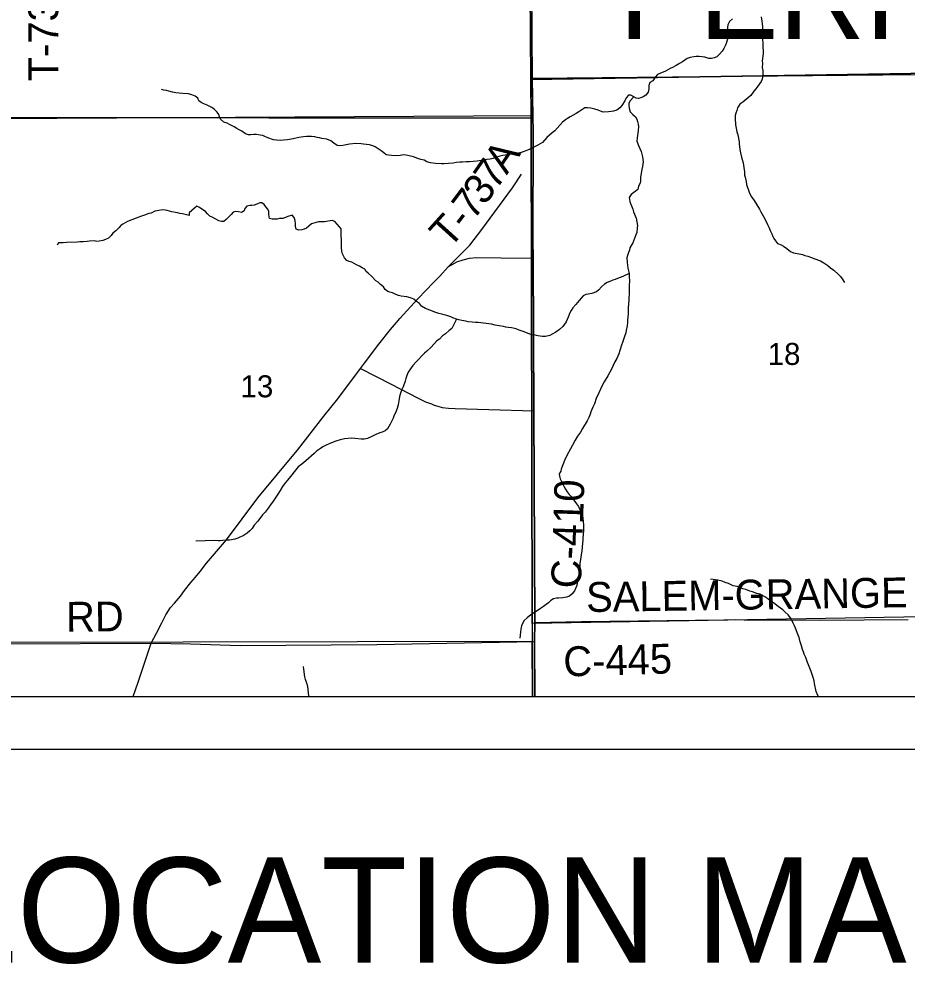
# Model space of a CAD drawing. Extents: x 0 to 34, y 0 to 22.
# Drawn here: x 4.579 to 6.27, y 13.591 to 15.389 of the extents above; entities that cross this region are included whole.
import ezdxf

# ---------------------------------------------------------------- set-up
doc = ezdxf.new("R2010")
doc.units = 0
for name, color, linetype in [('Default', 7, 'Continuous'), ('GM_X_County_Road', 7, 'Continuous'), ('GM_X_County_Road_Text', 7, 'Continuous'), ('GM_X_Minor_River', 7, 'Continuous'), ('GM_X_Rail_Line', 7, 'Continuous'), ('GM_X_Section', 7, 'Continuous'), ('GM_X_Section_Text', 7, 'Continuous'), ('GM_X_Township', 7, 'Continuous'), ('GM_X_Township_Road', 7, 'Continuous'), ('GM_X_Township_Road_Text', 7, 'Continuous'), ('GM_X_Township_Text', 7, 'Continuous'), ('SH_Cut_Line', 7, 'Continuous'), ('SH_Data', 7, 'Continuous'), ('SH_Text', 7, 'Continuous')]:
    doc.layers.add(name, color=color, linetype=linetype)

msp = doc.modelspace()

# ---------------------------------------------------------------- linework, layer by layer
at = {"layer": 'Default'}
for points in [[(5.5573, 14.1), (6.527, 14.1), (6.5252, 14.2552), (5.5565, 14.239), (5.5568, 14.2045)], [(4.5592, 14.1), (5.5573, 14.1), (5.5568, 14.2045), (4.5597, 14.2026)]]:
    msp.add_lwpolyline(points, close=True, dxfattribs=at)
at = {"layer": 'GM_X_County_Road'}
for points in [[(5.5581, 15.2023), (5.5581, 15.2044), (5.5571, 15.2755), (5.5558, 15.4469), (5.5556, 15.5593)], [(5.5617, 14.2409), (5.5597, 14.6434), (5.5585, 14.9341), (5.5583, 14.9671), (5.559, 15.1741), (5.5581, 15.2023)], [(5.5617, 14.2409), (5.6505, 14.2428), (5.9216, 14.2459), (5.9435, 14.2467), (5.9605, 14.2462), (6.1042, 14.2452), (6.2723, 14.2468)], [(5.5621, 14.1), (5.561, 14.2045), (5.5617, 14.2409)]]:
    msp.add_lwpolyline(points, dxfattribs=at)
at = {"layer": 'GM_X_Minor_River'}
for points in [[(5.9378, 15.3897), (5.9323, 15.3846), (5.929, 15.3781), (5.9287, 15.3735), (5.9288, 15.3682), (5.9293, 15.3636), (5.9294, 15.3587), (5.9291, 15.3534), (5.9266, 15.3446), (5.9245, 15.3392), (5.9212, 15.3327), (5.9183, 15.328), (5.9135, 15.3222), (5.9079, 15.3172), (5.9034, 15.3152), (5.8981, 15.3139), (5.8928, 15.3142), (5.8856, 15.3163), (5.8802, 15.3173), (5.8746, 15.318), (5.8689, 15.3178), (5.8647, 15.3174), (5.8576, 15.3157), (5.8519, 15.3137), (5.843, 15.3074), (5.8373, 15.3046), (5.8306, 15.3007), (5.8239, 15.2971), (5.8194, 15.2947), (5.8104, 15.2896), (5.7995, 15.2851), (5.795, 15.2835), (5.7905, 15.2785), (5.7861, 15.2715), (5.7809, 15.2684), (5.7787, 15.2623), (5.7789, 15.2562), (5.7775, 15.2497), (5.7731, 15.2439), (5.7682, 15.2407), (5.7633, 15.2391), (5.7592, 15.2379), (5.7546, 15.2382), (5.75, 15.2411), (5.7443, 15.2444), (5.7401, 15.2439), (5.7357, 15.2393), (5.7328, 15.2331), (5.7273, 15.2246), (5.7232, 15.22), (5.7176, 15.2153), (5.7112, 15.2136), (5.7071, 15.2128), (5.7021, 15.2123), (5.6915, 15.2121), (5.6866, 15.2135), (5.682, 15.2153), (5.6759, 15.2178), (5.6683, 15.2196), (5.6622, 15.2202), (5.6569, 15.2201), (5.6513, 15.2165), (5.6457, 15.2126), (5.6405, 15.2094), (5.6348, 15.2063), (5.6289, 15.2027), (5.624, 15.2), (5.6199, 15.1972), (5.6143, 15.1929), (5.6095, 15.1871), (5.5995, 15.1766), (5.5946, 15.1723), (5.5894, 15.168), (5.5846, 15.1634), (5.5765, 15.1544), (5.5675, 15.1489), (5.5596, 15.1453), (5.5555, 15.1429), (5.548, 15.1394), (5.5412, 15.1369), (5.5356, 15.1353), (5.5307, 15.1337), (5.5243, 15.1331), (5.5141, 15.1314), (5.5099, 15.1306), (5.5009, 15.1292)], [(5.9923, 15.3931), (5.994, 15.3852), (5.9949, 15.375), (5.9951, 15.3681), (5.9956, 15.3639), (5.9953, 15.3594), (5.9958, 15.3339), (5.9963, 15.3297), (5.9964, 15.3233), (5.9948, 15.3092), (5.9949, 15.3046), (5.9947, 15.2966), (5.9956, 15.2909), (5.9957, 15.2841), (5.9948, 15.2749), (5.9926, 15.2699), (5.9863, 15.2614), (5.9826, 15.256), (5.9789, 15.2518), (5.9727, 15.2433), (5.9656, 15.237), (5.9578, 15.2308), (5.9522, 15.2269), (5.9478, 15.2199), (5.946, 15.2149), (5.9446, 15.21), (5.9432, 15.2054), (5.9429, 15.1997), (5.9439, 15.1879), (5.9448, 15.1811), (5.9461, 15.1746), (5.9481, 15.1686), (5.9507, 15.1553), (5.9507, 15.1508), (5.9512, 15.1466), (5.9521, 15.1409), (5.9534, 15.1345), (5.9554, 15.1265), (5.9563, 15.1216), (5.9583, 15.1152), (5.9588, 15.111), (5.9596, 15.1065), (5.9606, 15.0981), (5.9611, 15.0921), (5.9619, 15.0879), (5.964, 15.0796), (5.9645, 15.0739), (5.9705, 15.058), (5.9744, 15.0509), (5.9795, 15.0438), (5.9893, 15.0273), (5.9921, 15.022), (5.9948, 15.0175), (5.9995, 15.0089), (6.0047, 14.9983), (6.0071, 14.9927), (6.0098, 14.9866), (6.013, 14.9802), (6.0146, 14.9753), (6.017, 14.9712), (6.0197, 14.9671), (6.024, 14.9622), (6.0309, 14.9593), (6.0351, 14.9571), (6.0412, 14.9523), (6.0485, 14.9468), (6.0543, 14.9439), (6.0649, 14.9422), (6.0714, 14.9408), (6.076, 14.9394), (6.0813, 14.938), (6.0885, 14.9355), (6.0927, 14.9337), (6.1053, 14.929), (6.1119, 14.9254), (6.1192, 14.9202), (6.1246, 14.9154), (6.1307, 14.9109), (6.1396, 14.9031), (6.1435, 14.899), (6.147, 14.8949), (6.1513, 14.8878)], [(5.5009, 15.1292), (5.4952, 15.1279), (5.4884, 15.1259), (5.482, 15.1239), (5.4764, 15.1226), (5.47, 15.1217), (5.4654, 15.1205), (5.4598, 15.12), (5.4522, 15.1186), (5.4443, 15.1177), (5.4375, 15.1172), (5.4307, 15.117), (5.4242, 15.1165), (5.4186, 15.1164), (5.4121, 15.1159), (5.4061, 15.115), (5.3887, 15.1135), (5.3841, 15.1134), (5.3724, 15.1143), (5.3633, 15.1156), (5.356, 15.1173), (5.3511, 15.1203), (5.3446, 15.1216), (5.3389, 15.1238), (5.3308, 15.127), (5.3225, 15.1288), (5.3168, 15.1302), (5.3118, 15.1304), (5.305, 15.1295), (5.2975, 15.129), (5.2891, 15.1292), (5.2831, 15.1298), (5.2789, 15.1309), (5.2739, 15.1342), (5.2692, 15.1382), (5.2635, 15.1423), (5.2577, 15.1456), (5.2531, 15.1478), (5.2467, 15.1499), (5.2356, 15.1512), (5.2311, 15.1515), (5.2212, 15.152), (5.2091, 15.151), (5.1963, 15.1485), (5.1903, 15.1479), (5.1853, 15.1482), (5.1788, 15.153), (5.173, 15.1571), (5.1654, 15.1603), (5.1563, 15.162), (5.1517, 15.1631), (5.1471, 15.1637), (5.1429, 15.1648), (5.1365, 15.1658), (5.127, 15.1652), (5.121, 15.1647), (5.1127, 15.1637), (5.1014, 15.1612), (5.0908, 15.1591), (5.0829, 15.1585), (5.0772, 15.158), (5.07, 15.1586), (5.0639, 15.1593), (5.0532, 15.1628), (5.0479, 15.1654), (5.0437, 15.1672), (5.0387, 15.1682), (5.0319, 15.1692), (5.0266, 15.1691), (5.0209, 15.1686), (5.0164, 15.1689), (5.011, 15.1703), (5.0037, 15.1754), (4.9987, 15.1784), (4.9945, 15.1806), (4.9892, 15.1839), (4.9807, 15.1883), (4.9761, 15.1908), (4.9693, 15.193), (4.9635, 15.1985), (4.9615, 15.2031), (4.9599, 15.2076), (4.9571, 15.2121), (4.9517, 15.2169), (4.9467, 15.2206), (4.9379, 15.225), (4.9318, 15.2275), (4.9265, 15.2301), (4.9222, 15.2334), (4.9198, 15.2383), (4.9148, 15.2423), (4.9087, 15.2449), (4.9026, 15.2466), (4.8916, 15.2472), (4.8848, 15.2478), (4.878, 15.2488), (4.8719, 15.2498), (4.8646, 15.2519), (4.8605, 15.253), (4.8555, 15.2536), (4.8509, 15.255)], [(5.75, 15.2411), (5.7426, 15.233), (5.7408, 15.2284), (5.7405, 15.2242), (5.741, 15.2192), (5.7434, 15.2124), (5.7481, 15.2072), (5.7531, 15.2028), (5.7558, 15.1983), (5.7574, 15.1941), (5.7587, 15.1888), (5.7592, 15.1843), (5.7586, 15.177), (5.7569, 15.1675), (5.7562, 15.1629), (5.7559, 15.1568), (5.7591, 15.1485), (5.7619, 15.1425), (5.7643, 15.1368), (5.7668, 15.1266), (5.7677, 15.1171), (5.7664, 15.1084), (5.7654, 15.1026), (5.764, 15.0958), (5.7631, 15.0874), (5.7628, 15.0813), (5.7622, 15.0767), (5.7589, 15.0709), (5.7575, 15.0644), (5.7452, 15.0554), (5.7415, 15.0496), (5.7428, 15.0421), (5.744, 15.0379), (5.7456, 15.0338), (5.748, 15.027), (5.7497, 15.0221), (5.7544, 15.0104), (5.7561, 15.0032), (5.757, 14.996), (5.7567, 14.9918), (5.7558, 14.983), (5.754, 14.9784), (5.7522, 14.9731), (5.7482, 14.9635), (5.7427, 14.9535), (5.7417, 14.9493), (5.7399, 14.9447), (5.7381, 14.9393), (5.7371, 14.9347), (5.7372, 14.9263), (5.7381, 14.9203), (5.739, 14.915), (5.7402, 14.9101), (5.7411, 14.9048), (5.7416, 14.9002), (5.7418, 14.8888), (5.7415, 14.8842), (5.7416, 14.88), (5.7411, 14.8698), (5.7406, 14.8545), (5.74, 14.8465), (5.7394, 14.8397), (5.7392, 14.8332), (5.7393, 14.8287), (5.7387, 14.8214), (5.7384, 14.8165), (5.7381, 14.8119), (5.7375, 14.805), (5.7358, 14.7966), (5.7347, 14.7921), (5.7322, 14.7852), (5.7305, 14.779), (5.7287, 14.7737), (5.7269, 14.7687), (5.7237, 14.7583), (5.7216, 14.7518), (5.7176, 14.743), (5.7139, 14.7365), (5.711, 14.7299), (5.7074, 14.7226), (5.7005, 14.7103), (5.6935, 14.6988), (5.6895, 14.6903), (5.6866, 14.6845), (5.6837, 14.6776), (5.6786, 14.6669), (5.6754, 14.6569), (5.6722, 14.6508), (5.6686, 14.6416), (5.6671, 14.6373), (5.6646, 14.6308), (5.6613, 14.6247), (5.6525, 14.61), (5.6485, 14.6031), (5.643, 14.5954), (5.6382, 14.5877), (5.6335, 14.578), (5.6299, 14.5715), (5.6229, 14.5584), (5.6182, 14.5492), (5.6153, 14.5411)], [(5.1808, 15.004), (5.1758, 15.0054), (5.1611, 15.0032), (5.1558, 15.0031), (5.1501, 15.0033), (5.1411, 15.0005), (5.1362, 14.9992), (5.1313, 14.9946), (5.1269, 14.9914), (5.1227, 14.989), (5.1178, 14.9878), (5.1122, 14.9873), (5.1076, 14.9891), (5.1063, 14.9948), (5.1062, 14.9993), (5.1054, 15.0054), (5.1037, 15.0114), (5.0998, 15.0159), (5.0916, 15.0135), (5.087, 15.0115), (5.0818, 15.0098), (5.0754, 15.0093), (5.0712, 15.0085), (5.0617, 15.0083), (5.0568, 15.0093), (5.0555, 15.0172), (5.055, 15.0226), (5.0534, 15.0271), (5.0495, 15.0319), (5.0464, 15.0364), (5.0422, 15.039), (5.038, 15.0393), (5.0327, 15.0369), (5.0271, 15.0349), (5.0229, 15.034), (5.0188, 15.0343), (5.0135, 15.0331), (5.0098, 15.0284), (5.008, 15.0238), (5.0032, 15.0207), (4.9974, 15.0224), (4.9925, 15.0231), (4.9876, 15.0215), (4.9835, 15.0168), (4.9791, 15.0125), (4.9743, 15.0075), (4.9698, 15.004), (4.9649, 15.0039), (4.9603, 15.0049), (4.9534, 15.0089), (4.9488, 15.0115), (4.9431, 15.0137), (4.9384, 15.0185), (4.9345, 15.023), (4.9299, 15.0263), (4.923, 15.0307), (4.9184, 15.0329), (4.9136, 15.0294), (4.9039, 15.02), (4.9033, 15.0155), (4.8911, 15.0186), (4.8861, 15.0193), (4.8816, 15.0203), (4.8774, 15.021), (4.8706, 15.0223), (4.866, 15.0234), (4.8618, 15.0248), (4.8576, 15.0255), (4.8527, 15.0261), (4.8459, 15.0245), (4.8383, 15.0232), (4.8312, 15.0196), (4.8267, 15.0187), (4.8184, 15.0159), (4.8128, 15.0139), (4.803, 15.0099), (4.7865, 15.0038), (4.7775, 14.999), (4.7734, 14.9959), (4.7697, 14.9916), (4.7641, 14.9862), (4.7585, 14.9815), (4.7548, 14.9772), (4.75, 14.9722), (4.7444, 14.9694), (4.7395, 14.9678), (4.7323, 14.9665), (4.7278, 14.966), (4.7225, 14.9667), (4.7138, 14.9665), (4.7092, 14.966), (4.7021, 14.9651), (4.6956, 14.9649), (4.6907, 14.9644), (4.6699, 14.964), (4.6635, 14.9635), (4.6593, 14.963), (4.6548, 14.9633), (4.6522, 14.9587)], [(5.7411, 14.9048), (5.7295, 14.8992), (5.7242, 14.8975), (5.719, 14.8955), (5.7148, 14.8935), (5.7103, 14.8919), (5.7043, 14.8899), (5.6994, 14.8875), (5.6942, 14.8843), (5.6886, 14.8797), (5.6834, 14.8738), (5.6793, 14.8699), (5.6703, 14.8667), (5.6635, 14.8654), (5.659, 14.8646), (5.6537, 14.8625), (5.646, 14.8536), (5.6397, 14.8459), (5.6341, 14.8393), (5.6308, 14.8343), (5.6283, 14.8297), (5.625, 14.8216), (5.6214, 14.8132), (5.6148, 14.8039), (5.6089, 14.7984), (5.6018, 14.7933), (5.5947, 14.7894), (5.5902, 14.7866), (5.5819, 14.7849), (5.5766, 14.7848), (5.5716, 14.7858), (5.5671, 14.7865), (5.5621, 14.7875), (5.5564, 14.7882), (5.5519, 14.7896), (5.5415, 14.7939), (5.532, 14.7972), (5.5263, 14.7993), (5.5171, 14.8014), (5.5107, 14.8024), (5.5065, 14.8027), (5.5023, 14.8037), (5.494, 14.8051), (5.4863, 14.8068), (5.4791, 14.8082), (5.4537, 14.8114), (5.4487, 14.8117), (5.4423, 14.8123), (5.4347, 14.8129), (5.4305, 14.814), (5.4229, 14.8157), (5.4172, 14.8167), (5.4123, 14.8181), (5.4058, 14.8207), (5.4016, 14.8225), (5.3939, 14.825), (5.389, 14.8264), (5.3848, 14.8274), (5.3787, 14.8288), (5.3734, 14.8306), (5.3619, 14.8349), (5.3535, 14.8385), (5.3462, 14.8429), (5.3423, 14.8478), (5.3362, 14.8518), (5.3316, 14.8559), (5.3251, 14.8584), (5.3178, 14.8602), (5.3072, 14.8615), (5.3019, 14.8629), (5.2973, 14.8647), (5.2904, 14.868), (5.2858, 14.8694), (5.2816, 14.8708), (5.2766, 14.8745), (5.2735, 14.8798), (5.2677, 14.8842), (5.2635, 14.8883), (5.2589, 14.8912), (5.2515, 14.8991), (5.2445, 14.9054), (5.2403, 14.9087), (5.238, 14.9128), (5.233, 14.9154), (5.2276, 14.9191), (5.2222, 14.9216), (5.2131, 14.9264), (5.2081, 14.9274), (5.2035, 14.9296), (5.1992, 14.9348), (5.1953, 14.9423), (5.1941, 14.9472), (5.1935, 14.9545), (5.1934, 14.9586), (5.1937, 14.9628), (5.1936, 14.9708), (5.1931, 14.9754), (5.1929, 14.9856), (5.1932, 14.9898), (5.1897, 14.9939), (5.1808, 15.004)], [(5.4123, 14.8181), (5.4039, 14.8005), (5.3983, 14.7965), (5.3913, 14.7899), (5.386, 14.786), (5.3805, 14.7802), (5.3749, 14.7766), (5.3641, 14.7646), (5.356, 14.7568), (5.3519, 14.7533), (5.3467, 14.7479), (5.34, 14.7413), (5.3355, 14.7366), (5.3296, 14.73), (5.3208, 14.7169), (5.3183, 14.7111), (5.3161, 14.705), (5.3147, 14.7), (5.3108, 14.6893), (5.3082, 14.6839), (5.3061, 14.677), (5.3043, 14.6709), (5.303, 14.6625), (5.3016, 14.6549), (5.2995, 14.648), (5.2963, 14.6399), (5.2941, 14.6353), (5.2919, 14.6299), (5.2865, 14.6184), (5.2814, 14.6096), (5.2765, 14.6057), (5.2709, 14.6032), (5.2664, 14.6016), (5.2593, 14.5984), (5.2525, 14.5952), (5.2431, 14.5912), (5.2367, 14.5896), (5.231, 14.5895), (5.2193, 14.5911), (5.2128, 14.5913), (5.1996, 14.5903), (5.1909, 14.5886), (5.1826, 14.5857), (5.1717, 14.5813), (5.1631, 14.5773), (5.1582, 14.5749), (5.1538, 14.5722), (5.1459, 14.5667), (5.1418, 14.5624), (5.1258, 14.5484), (5.118, 14.5421), (5.1113, 14.5367), (5.1061, 14.5308), (5.0965, 14.5188), (5.091, 14.5115), (5.0847, 14.5041), (5.0814, 14.4995), (5.077, 14.4922), (5.0722, 14.4852), (5.0686, 14.4791), (5.0638, 14.4717), (5.0587, 14.4644), (5.0539, 14.4582), (5.0483, 14.4509), (5.0435, 14.4458), (5.0343, 14.4338), (5.0276, 14.4261), (5.0236, 14.4199), (5.0192, 14.4152), (5.0139, 14.411), (5.0065, 14.4058), (5.0001, 14.403), (4.996, 14.4011), (4.9907, 14.3994), (4.9843, 14.3981), (4.9801, 14.3977), (4.9748, 14.3976), (4.9676, 14.397), (4.9627, 14.3965), (4.9586, 14.3964), (4.9521, 14.3967), (4.9165, 14.3959)], [(5.6153, 14.5411), (5.6117, 14.5327), (5.6111, 14.5285), (5.6081, 14.5235), (5.6086, 14.5193), (5.6102, 14.5144), (5.615, 14.5043), (5.6174, 14.499), (5.6201, 14.4945), (5.6232, 14.4896), (5.6271, 14.4844), (5.6337, 14.4788), (5.6361, 14.4739), (5.6408, 14.4668), (5.6446, 14.4615), (5.6506, 14.4495), (5.6522, 14.4442), (5.6531, 14.4389), (5.6545, 14.4264), (5.6546, 14.4211), (5.6543, 14.4165), (5.6537, 14.4077), (5.6531, 14.402), (5.6528, 14.3971), (5.6522, 14.3921), (5.6513, 14.3765), (5.65, 14.3704), (5.6493, 14.3647), (5.6476, 14.354), (5.6474, 14.349), (5.6468, 14.3422), (5.6455, 14.3315), (5.6434, 14.3231), (5.642, 14.3158), (5.6417, 14.3113), (5.637, 14.3013), (5.6326, 14.2955), (5.6274, 14.2912), (5.6217, 14.2888), (5.6149, 14.2875), (5.607, 14.2873), (5.6028, 14.2869), (5.5972, 14.2856), (5.5923, 14.2828), (5.5875, 14.2785), (5.5834, 14.2754), (5.5785, 14.2715), (5.5726, 14.2672), (5.5681, 14.2644), (5.5557, 14.2569), (5.5509, 14.253), (5.5468, 14.2495), (5.5416, 14.2445), (5.539, 14.2402), (5.5365, 14.2348), (5.5351, 14.228), (5.5345, 14.223), (5.5335, 14.2165), (5.5332, 14.2108)], [(6.1015, 14.1), (6.1002, 14.1022), (6.0974, 14.1094), (6.0944, 14.1249), (6.0932, 14.1298), (6.0915, 14.1359), (6.0875, 14.1476), (6.0827, 14.1604), (6.0807, 14.1645), (6.0787, 14.1702), (6.0775, 14.1743), (6.0747, 14.1804), (6.0731, 14.1853), (6.0711, 14.1894), (6.0694, 14.1966), (6.0666, 14.2042), (6.065, 14.2121), (6.063, 14.2166), (6.0578, 14.2302), (6.0561, 14.2347), (6.0538, 14.2396), (6.0514, 14.2441), (6.0483, 14.2498), (6.044, 14.2554), (6.0378, 14.2613), (6.0336, 14.265), (6.0293, 14.268), (6.0247, 14.2713), (6.0162, 14.278), (6.0093, 14.2828), (6.0051, 14.2861), (5.9993, 14.2898), (5.9905, 14.2945), (5.9844, 14.2959), (5.9764, 14.2995), (5.9711, 14.3006), (5.9634, 14.3038), (5.9577, 14.3052), (5.9535, 14.3066), (5.947, 14.3095), (5.9394, 14.3109), (5.9352, 14.3123), (5.9302, 14.3153), (5.9241, 14.317), (5.9184, 14.3196), (5.9104, 14.3217), (5.9055, 14.3223), (5.9009, 14.3226), (5.896, 14.3233)], [(5.1316, 14.1), (5.1313, 14.1017), (5.1309, 14.1062), (5.1304, 14.1131), (5.1295, 14.1188), (5.1278, 14.1256), (5.125, 14.1327), (5.1238, 14.1373), (5.1229, 14.1422), (5.1224, 14.1479), (5.1216, 14.1521), (5.1211, 14.157)]]:
    msp.add_lwpolyline(points, dxfattribs=at)
at = {"layer": 'GM_X_Rail_Line'}
for points in [[(5.5619, 14.1), (8.9, 14.1), (8.9, 17.3138), (8.2882, 17.3064), (7.4754, 17.3006), (7.4757, 17.0495), (7.4723, 16.4951), (7.4818, 15.827), (7.482, 15.8179), (7.4834, 15.2992), (7.3416, 15.297), (6.5709, 15.2859), (6.3575, 15.2833), (5.5569, 15.2761), (5.5579, 15.2049), (5.5588, 15.1747), (5.5581, 14.9676), (5.5583, 14.9347), (5.5595, 14.6439), (5.5615, 14.2414), (5.5608, 14.205)], [(2.1, 17.2107), (2.1, 14.1), (5.5619, 14.1), (5.5608, 14.205), (5.5615, 14.2414), (5.5595, 14.6439), (5.5583, 14.9347), (5.5581, 14.9676), (5.5588, 15.1747), (5.5579, 15.2049), (4.0847, 15.1965), (3.5411, 15.1931), (3.5298, 15.9318), (3.5269, 16.3549), (3.511, 17.2267), (3.4711, 17.2262), (2.9494, 17.2203), (2.5218, 17.2155)]]:
    msp.add_lwpolyline(points, close=True, dxfattribs=at)
at = {"layer": 'GM_X_Section'}
for points in [[(5.5468, 16.2132), (6.5053, 16.2508), (6.5184, 15.2893), (5.5538, 15.2739)], [(4.5462, 16.1923), (5.5468, 16.2132), (5.5538, 15.2739), (5.5548, 15.2004), (4.5552, 15.2018)], [(5.5538, 15.2739), (6.5184, 15.2893), (6.5252, 14.2552), (5.5565, 14.239), (5.5548, 15.2004)], [(4.5552, 15.2018), (5.5548, 15.2004), (5.5565, 14.239), (5.5568, 14.2045), (4.5597, 14.2026)]]:
    msp.add_lwpolyline(points, close=True, dxfattribs=at)
at = {"layer": 'GM_X_Township'}
msp.add_lwpolyline([(7.482, 15.8179), (7.4834, 15.2992), (7.3416, 15.297), (6.5709, 15.2859), (6.3575, 15.2833), (5.5569, 15.2761), (5.5579, 15.2049), (4.0847, 15.1965), (3.5411, 15.1931), (3.5298, 15.9318)], dxfattribs=at)
at = {"layer": 'GM_X_Township_Road'}
msp.add_line((5.3965, 14.9176), (5.4282, 14.9493), dxfattribs=at)
for points in [[(5.4282, 14.9493), (5.4377, 14.9588), (5.461, 14.9886), (5.5192, 15.0678), (5.536, 15.0941)], [(5.1093, 14.5679), (5.1098, 14.5685), (5.16, 14.6332), (5.1866, 14.6667), (5.2296, 14.7238), (5.2373, 14.7342), (5.2645, 14.7704), (5.2872, 14.7984), (5.2986, 14.8119), (5.3048, 14.819), (5.3183, 14.834), (5.3398, 14.857), (5.3687, 14.8877), (5.3807, 14.9), (5.3965, 14.9176), (5.4134, 14.9272), (5.4253, 14.9309), (5.437, 14.9339), (5.4505, 14.935), (5.497, 14.9346), (5.5585, 14.9341)], [(5.2296, 14.7238), (5.2881, 14.6942), (5.3383, 14.6685), (5.3538, 14.661), (5.3647, 14.6567), (5.3699, 14.6545), (5.3772, 14.6524), (5.385, 14.6501), (5.3971, 14.6486), (5.41, 14.6479), (5.4738, 14.6461), (5.5597, 14.6434)], [(4.8099, 14.1371), (4.8315, 14.2014), (4.8411, 14.2203), (4.8513, 14.2402), (4.8592, 14.2555), (4.8682, 14.2693), (4.8754, 14.2776), (4.8868, 14.2911), (4.8946, 14.3016), (4.9068, 14.3169), (4.9158, 14.3274), (4.9248, 14.338), (4.9368, 14.3535), (4.9744, 14.3983), (5.0344, 14.478), (5.1093, 14.5679)], [(3.8615, 14.1974), (4.0624, 14.1963), (4.2539, 14.1985), (4.4042, 14.1993), (4.5616, 14.2005), (4.8315, 14.2014), (4.9063, 14.2005), (5.0007, 14.197), (5.2611, 14.1988), (5.561, 14.2045)], [(4.7973, 14.1), (4.8065, 14.127), (4.8099, 14.1371)]]:
    msp.add_lwpolyline(points, dxfattribs=at)
at = {"layer": 'SH_Cut_Line'}
msp.add_lwpolyline([(2.1, 17.2107), (2.1, 14.1), (8.9, 14.1)], dxfattribs=at)
at = {"layer": 'SH_Data'}
for p, q in [((2.1, 14.1), (8.9, 14.1)), ((2, 14), (9, 14))]:
    msp.add_line(p, q, dxfattribs=at)

# ---------------------------------------------------------------- texts
at = {"layer": 'GM_X_County_Road_Text'}
for s, height, rotation, p in [('C-410', 0.05682, 88.0725, (5.6492, 14.3051)), ('SALEM-GRANGE', 0.056818, 0.8685, (5.6597, 14.2607)), ('C-445', 0.05682, 1.6524, (5.6167, 14.138))]:
    msp.add_text(s, height=height, rotation=rotation, dxfattribs=at).set_placement(p)
at = {"layer": 'GM_X_Section_Text'}
for s, p in [('18', (6.0051, 14.7309)), ('13', (5.0014, 14.6693))]:
    msp.add_text(s, height=0.04186, rotation=0, dxfattribs=at).set_placement(p)
at = {"layer": 'GM_X_Township_Road_Text'}
for s, height, rotation, p in [('T-738', 0.05682, 90.0342, (4.6544, 15.2704)), ('A', 0.0568, 56.2034, (5.5082, 15.0913)), ('7', 0.0568, 55.1638, (5.4877, 15.0619)), ('3', 0.0568, 53.3504, (5.4658, 15.0324)), ('7', 0.0568, 53.0802, (5.4448, 15.0044)), ('T', 0.0568, 47.8947, (5.3987, 14.9503)), ('-', 0.0568, 52.425, (5.4303, 14.9855)), ('RD', 0.05682, 0.4936, (4.6695, 14.2232))]:
    msp.add_text(s, height=height, rotation=rotation, dxfattribs=at).set_placement(p)
at = {"layer": 'GM_X_Township_Text'}
msp.add_text('PERRY', height=0.17045, rotation=0, dxfattribs=at).set_placement((5.7217, 15.3511))
at = {"layer": 'SH_Text'}
msp.add_text('LOCATION MAP', height=0.2, dxfattribs=at).set_placement((4.4269, 13.5938))

doc.saveas('drawing.dxf')
